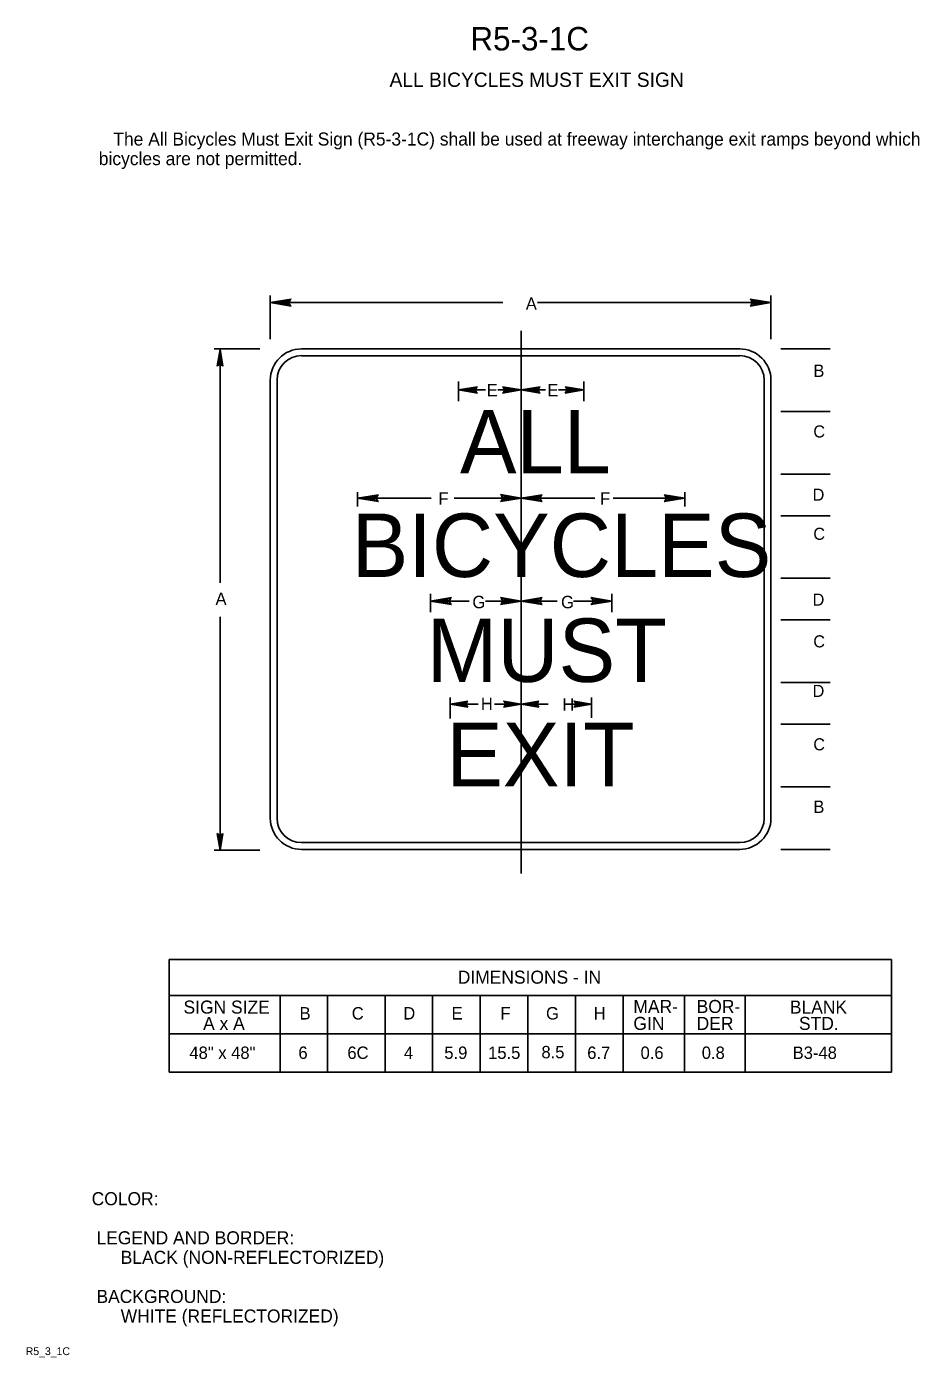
# Model space of a CAD drawing. Extents: x 0.013 to 0.184, y 0.004 to 0.259.
import ezdxf

# ---------------------------------------------------------------- set-up
doc = ezdxf.new("R2010")
doc.units = 0
for name, color, linetype in [('1', 7, 'Continuous'), ('11', 7, 'Continuous'), ('12', 7, 'Continuous'), ('2', 7, 'Continuous'), ('3', 7, 'Continuous')]:
    doc.layers.add(name, color=color, linetype=linetype)

# ---------------------------------------------------------------- blocks, each defined once
blk = doc.blocks.new('RARROW')
at = {"layer": '3'}
for p, q in [((-2.156, 0.285), (-2.2665, 0.384625)), ((-2.2665, 0.384625), (0, 0)), ((0, 0), (-2.2665, -0.379125)), ((-2.156, 0.285), (-2.075625, 0.12075)), ((0, 0), (-2.156, 0.285)), ((-2.14975, -0.2705), (0, 0)), ((-2.075625, 0.12075), (0, 0)), ((0, 0), (-2.074, -0.108)), ((-2.2665, -0.379125), (-2.14975, -0.2705)), ((-2.074, -0.108), (-2.14975, -0.2705))]:
    blk.add_line(p, q, dxfattribs=at)

msp = doc.modelspace()

# ---------------------------------------------------------------- linework, layer by layer
at = {"layer": '11'}
msp.add_line((0.05938, 0.19138), (0.05938, 0.19138), dxfattribs=at)
at = {"layer": '3'}
for p, q in [((0.05938, 0.19925), (0.05938, 0.20763)), ((0.15538, 0.19925), (0.15538, 0.20763)), ((0.104, 0.20625), (0.05938, 0.20625)), ((0.11063, 0.20625), (0.15538, 0.20625)), ((0.1075, 0.20087), (0.1075, 0.09675)), ((0.05738, 0.19737), (0.04863, 0.19737)), ((0.04975, 0.1525), (0.04975, 0.19737)), ((0.06538, 0.19737), (0.14938, 0.19737)), ((0.15725, 0.19737), (0.16675, 0.19737)), ((0.06538, 0.19607), (0.14938, 0.19607)), ((0.05938, 0.10737), (0.05938, 0.19138)), ((0.06068, 0.10737), (0.06068, 0.19138)), ((0.0955, 0.18738), (0.0955, 0.19113)), ((0.10063, 0.1895), (0.0955, 0.1895)), ((0.1075, 0.1895), (0.103, 0.1895)), ((0.1075, 0.18738), (0.1075, 0.19113)), ((0.11213, 0.1895), (0.1075, 0.1895)), ((0.1195, 0.1895), (0.11463, 0.1895)), ((0.1195, 0.18738), (0.1195, 0.19113)), ((0.15407, 0.19138), (0.15407, 0.10737)), ((0.15538, 0.19138), (0.15538, 0.10737)), ((0.15725, 0.18538), (0.16675, 0.18538)), ((0.15725, 0.17338), (0.16675, 0.17338)), ((0.07612, 0.16987), (0.07612, 0.16712)), ((0.09025, 0.16875), (0.07612, 0.16875)), ((0.09463, 0.16875), (0.1075, 0.16875)), ((0.1075, 0.16987), (0.1075, 0.16712)), ((0.12162, 0.16875), (0.1075, 0.16875)), ((0.12513, 0.16875), (0.13887, 0.16875)), ((0.13887, 0.16987), (0.13887, 0.16712)), ((0.15725, 0.16537), (0.16675, 0.16537)), ((0.15725, 0.15338), (0.16675, 0.15338)), ((0.09012, 0.14688), (0.09012, 0.15038)), ((0.09012, 0.149), (0.0975, 0.149)), ((0.10063, 0.149), (0.1075, 0.149)), ((0.1075, 0.14688), (0.1075, 0.1505)), ((0.11438, 0.149), (0.1075, 0.149)), ((0.12487, 0.149), (0.1175, 0.149)), ((0.12487, 0.14688), (0.12487, 0.15038)), ((0.04975, 0.146), (0.04975, 0.10138)), ((0.15725, 0.14538), (0.16675, 0.14538)), ((0.15725, 0.13337), (0.16675, 0.13337)), ((0.09388, 0.1265), (0.09388, 0.1305)), ((0.1075, 0.12688), (0.1075, 0.1305)), ((0.121, 0.12663), (0.121, 0.1305)), ((0.09388, 0.12925), (0.09925, 0.12925)), ((0.10238, 0.12925), (0.1075, 0.12925)), ((0.11263, 0.12925), (0.1075, 0.12925)), ((0.121, 0.12925), (0.11575, 0.12925)), ((0.15725, 0.12538), (0.16675, 0.12538)), ((0.15725, 0.11338), (0.16675, 0.11338)), ((0.14938, 0.10268), (0.06538, 0.10268)), ((0.05738, 0.10125), (0.04863, 0.10125)), ((0.14938, 0.10138), (0.06538, 0.10138)), ((0.15725, 0.10138), (0.16675, 0.10138)), ((0.04, 0.08025), (0.1785, 0.08025)), ((0.04, 0.08025), (0.04, 0.05863)), ((0.1785, 0.08025), (0.1785, 0.05863)), ((0.04, 0.07337), (0.1785, 0.07337)), ((0.06129, 0.07337), (0.06129, 0.05862)), ((0.07038, 0.07337), (0.07038, 0.05863)), ((0.08138, 0.07337), (0.08138, 0.05863)), ((0.0905, 0.07337), (0.0905, 0.05863)), ((0.09963, 0.07337), (0.09963, 0.05863)), ((0.10875, 0.07337), (0.10875, 0.05863)), ((0.11788, 0.07337), (0.11788, 0.05863)), ((0.12704, 0.07337), (0.12704, 0.05862)), ((0.13879, 0.07337), (0.13879, 0.05862)), ((0.15042, 0.07337), (0.15042, 0.05862)), ((0.04, 0.066), (0.1785, 0.066)), ((0.04, 0.05863), (0.1785, 0.05863))]:
    msp.add_line(p, q, dxfattribs=at)
for centre, radius, start, end in [((0.06538, 0.19138), 0.006, 90, 180), ((0.14938, 0.19138), 0.006, 0, 90), ((0.06538, 0.19138), 0.0047, 90, 180), ((0.14938, 0.19138), 0.0047, 0, 90), ((0.06538, 0.10737), 0.006, 180, 270), ((0.06538, 0.10737), 0.0047, 180, 270), ((0.14938, 0.10737), 0.006, 270, 0), ((0.14938, 0.10737), 0.0047, 270, 0)]:
    msp.add_arc(centre, radius, start, end, dxfattribs=at)

# ---------------------------------------------------------------- block references
for p, xscale, yscale, rotation in [((0.05938, 0.20625), 0.0017647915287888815, 0.0017457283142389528, 180), ((0.04975, 0.19725), 0.0014118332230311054, 0.0013965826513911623, 90), ((0.0955, 0.1895), 0.0015883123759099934, 0.0015711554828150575, 180), ((0.1075, 0.1895), 0.0015883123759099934, 0.0015711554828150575, 180), ((0.07612, 0.16875), 0.0017647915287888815, 0.0017457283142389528, 180), ((0.1075, 0.16875), 0.0017647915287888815, 0.0017457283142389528, 180), ((0.09012, 0.149), 0.0017647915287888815, 0.0017457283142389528, 180), ((0.1075, 0.149), 0.0017647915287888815, 0.0017457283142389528, 180), ((0.09388, 0.12925), 0.0015000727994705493, -0.0014838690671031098, 180), ((0.1075, 0.12925), 0.0015000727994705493, 0.0014838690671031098, 180), ((0.04975, 0.10125), 0.0014118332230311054, 0.0013965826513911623, -90)]:
    msp.add_blockref('RARROW', p, dxfattribs=dict(at, xscale=xscale, yscale=yscale, rotation=rotation))
for p, xscale, yscale in [((0.15538, 0.20625), 0.0017647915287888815, 0.0017457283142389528), ((0.1075, 0.1895), 0.0015883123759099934, -0.0015711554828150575), ((0.1195, 0.1895), 0.0015883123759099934, -0.0015711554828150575), ((0.1075, 0.16875), 0.0017647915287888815, 0.0017457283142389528), ((0.13887, 0.16875), 0.0017647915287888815, -0.0017457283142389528), ((0.1075, 0.149), 0.0017647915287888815, 0.0017457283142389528), ((0.12487, 0.149), 0.0017647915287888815, -0.0017457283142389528), ((0.1075, 0.12925), 0.0015000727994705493, 0.0014838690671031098), ((0.121, 0.12925), 0.0015000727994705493, 0.0014838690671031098)]:
    msp.add_blockref('RARROW', p, dxfattribs=dict(at, xscale=xscale, yscale=yscale))

# ---------------------------------------------------------------- texts
at = {"layer": '1'}
for s, height, p in [('R5-3-1C', 0.0045, (0.09775, 0.25462)), ('ALL BICYCLES MUST EXIT SIGN', 0.0027503, (0.08225, 0.24763)), ('COLOR:', 0.0025, (0.02513, 0.03313)), (' LEGEND AND BORDER:', 0.0024998, (0.02513, 0.02563)), ('      BLACK (NON-REFLECTORIZED)', 0.0024998, (0.02513, 0.02188)), (' BACKGROUND:', 0.0024998, (0.02513, 0.01438)), ('      WHITE (REFLECTORIZED)', 0.0024998, (0.02513, 0.01063)), ('R5_3_1C', 0.0015, (0.0125, 0.00438))]:
    msp.add_text(s, height=height, dxfattribs=at).set_placement(p)
at = {"layer": '12'}
for s, p in [('ALL', (0.09575, 0.1735)), ('BICYCLES', (0.075, 0.15363)), ('MUST', (0.08937, 0.1335)), ('EXIT', (0.09312, 0.1135))]:
    msp.add_text(s, height=0.012161, dxfattribs=at).set_placement(p)
at = {"layer": '2'}
for s, height, p in [('   The All Bicycles Must Exit Sign (R5-3-1C) shall be used at freeway interchange exit ramps beyond which', 0.00249975, (0.0265, 0.23638)), ('bicycles are not permitted.', 0.0024998, (0.0265, 0.23262))]:
    msp.add_text(s, height=height, dxfattribs=at).set_placement(p)
at = {"layer": '3'}
for s, height, p in [('A', 0.00237, (0.10837, 0.20488)), ('B', 0.00238, (0.1635, 0.192)), ('E', 0.00238, (0.10088, 0.18825)), ('E', 0.00238, (0.1125, 0.18825)), ('C', 0.00232, (0.1635, 0.18038)), ('F', 0.00238, (0.09162, 0.1675)), ('F', 0.00238, (0.12262, 0.1675)), ('D', 0.00232, (0.16337, 0.16825)), ('C', 0.00232, (0.1635, 0.16075)), ('A', 0.00238, (0.04888, 0.14825)), ('G', 0.00238, (0.09813, 0.14763)), ('G', 0.00238, (0.11513, 0.14763)), ('D', 0.00232, (0.16337, 0.14813)), ('C', 0.00232, (0.1635, 0.14012)), ('D', 0.00232, (0.16337, 0.13062)), ('H', 0.00238, (0.09975, 0.12812)), ('H', 0.00238, (0.11538, 0.128)), ('C', 0.00232, (0.1635, 0.12037)), ('B', 0.00238, (0.1635, 0.10837)), ('DIMENSIONS - IN', 0.0024998, (0.09533, 0.07562)), ('SIGN SIZE', 0.0025, (0.04275, 0.06988)), ('MAR-', 0.0025, (0.129, 0.07)), ('BOR-', 0.0025, (0.14113, 0.07)), ('BLANK', 0.0025, (0.159, 0.06988)), ('A x A', 0.0025, (0.0465, 0.06675)), ('B', 0.00238, (0.065, 0.06875)), ('C', 0.00238, (0.075, 0.06875)), ('D', 0.00238, (0.08488, 0.06875)), ('E', 0.00238, (0.09413, 0.06875)), ('F', 0.00238, (0.1035, 0.06875)), ('G', 0.00238, (0.11225, 0.06875)), ('H', 0.00238, (0.12137, 0.06875)), ('GIN', 0.0025, (0.129, 0.06675)), ('DER', 0.0025, (0.14113, 0.06675)), ('STD.', 0.0025, (0.16075, 0.06675)), ('48" x 48"', 0.002375, (0.04387, 0.06119)), ('6', 0.00238, (0.06477, 0.06119)), ('6C', 0.002375, (0.07416, 0.06119)), ('4', 0.00238, (0.08501, 0.06119)), ('5.9', 0.002375, (0.09275, 0.06119)), ('15.5', 0.002375, (0.10115, 0.06119)), ('8.5', 0.002375, (0.11137, 0.06131)), ('6.7', 0.002375, (0.12015, 0.06119)), ('0.6', 0.002375, (0.13037, 0.06119)), ('0.8', 0.002375, (0.14211, 0.06119)), ('B3-48', 0.002375, (0.15954, 0.06119))]:
    msp.add_text(s, height=height, dxfattribs=at).set_placement(p)

doc.saveas('drawing.dxf')
